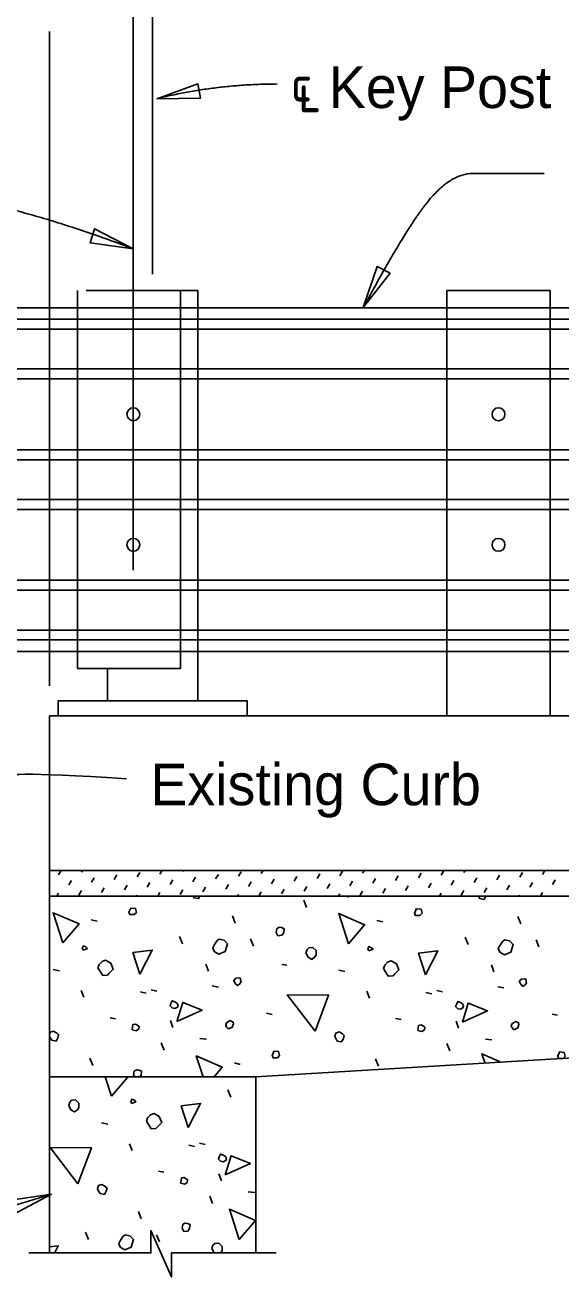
# Model space of a CAD drawing. Extents: x 21526.6 to 21598.7, y 56118.1 to 56155.9.
# Drawn here: x 21554.18 to 21556.78, y 56132.49 to 56138.56 of the extents above; entities that cross this region are included whole.
import ezdxf

# ---------------------------------------------------------------- set-up
doc = ezdxf.new("R2010")
doc.units = 0
for name, color, linetype in [('AdhocPoint_dp', 7, 'Continuous'), ('Border', 7, 'Continuous'), ('Patterning', 7, 'Continuous'), ('PlotBorder_dp', 7, 'Continuous'), ('SheetBorder_dp', 7, 'Continuous')]:
    doc.layers.add(name, color=color, linetype=linetype)

msp = doc.modelspace()

# ---------------------------------------------------------------- linework, layer by layer
at = {"layer": 'AdhocPoint_dp'}
for p, q in [((21554.3017, 56135.21), (21555.3017, 56135.21)), ((21554.3018, 56135.2101), (21554.3018, 56132.6054)), ((21554.3018, 56135.21), (21562.4118, 56135.21)), ((21565.8764, 56134.4601), (21554.3018, 56134.4601)), ((21554.3018, 56134.3351), (21565.8764, 56134.3351)), ((21559.5217, 56133.71), (21555.3017, 56133.4601)), ((21555.3017, 56133.46), (21554.3017, 56133.46)), ((21555.3017, 56133.4601), (21555.3017, 56132.6054))]:
    msp.add_line(p, q, dxfattribs=at)
at = {"layer": 'Patterning'}
for p, q in [((21554.7081, 56135.9163), (21554.7081, 56138.7275)), ((21554.8018, 56138.7275), (21554.8018, 56137.3509)), ((21554.4372, 56137.2725), (21554.4372, 56135.4392)), ((21554.479, 56137.2725), (21555.0205, 56137.2725)), ((21554.9372, 56137.2725), (21554.9372, 56135.4392)), ((21556.2288, 56137.2725), (21556.2288, 56135.21)), ((21556.2288, 56137.2725), (21556.7288, 56137.2725)), ((21556.7288, 56137.2725), (21556.7288, 56135.21)), ((21554.3461, 56134.4388), (21554.3585, 56134.4601)), ((21554.4568, 56134.4517), (21554.4616, 56134.4601)), ((21554.5056, 56134.4029), (21554.5186, 56134.4253)), ((21554.6162, 56134.4159), (21554.6292, 56134.4383)), ((21554.7269, 56134.4288), (21554.7398, 56134.4512)), ((21554.8375, 56134.4418), (21554.8481, 56134.4601)), ((21554.9481, 56134.4548), (21554.9512, 56134.4601)), ((21554.997, 56134.4059), (21555.0099, 56134.4283)), ((21555.1076, 56134.4189), (21555.1206, 56134.4413)), ((21555.2182, 56134.4319), (21555.2312, 56134.4542)), ((21555.3289, 56134.4448), (21555.3377, 56134.4601)), ((21555.4395, 56134.4578), (21555.4409, 56134.4601)), ((21555.4883, 56134.4089), (21555.5013, 56134.4313)), ((21555.599, 56134.4219), (21555.6119, 56134.4443)), ((21555.7096, 56134.4349), (21555.7226, 56134.4573)), ((21555.8202, 56134.4478), (21555.8273, 56134.4601)), ((21555.8691, 56134.399), (21555.882, 56134.4214)), ((21555.9797, 56134.412), (21555.9927, 56134.4344)), ((21556.0903, 56134.4249), (21556.1033, 56134.4473)), ((21556.201, 56134.4379), (21556.2138, 56134.4601)), ((21556.3116, 56134.4509), (21556.317, 56134.4601)), ((21556.3604, 56134.402), (21556.3734, 56134.4244)), ((21556.4711, 56134.415), (21556.484, 56134.4374)), ((21556.5817, 56134.428), (21556.5947, 56134.4503)), ((21556.6923, 56134.4409), (21556.7035, 56134.4601)), ((21554.395, 56134.3899), (21554.4079, 56134.4123)), ((21554.4438, 56134.3411), (21554.4568, 56134.3635)), ((21554.5544, 56134.3541), (21554.5674, 56134.3765)), ((21554.6651, 56134.367), (21554.678, 56134.3894)), ((21554.7757, 56134.38), (21554.7887, 56134.4024)), ((21554.8863, 56134.393), (21554.8993, 56134.4154)), ((21554.9352, 56134.3441), (21554.9481, 56134.3665)), ((21555.0458, 56134.3571), (21555.0588, 56134.3795)), ((21555.1564, 56134.3701), (21555.1694, 56134.3925)), ((21555.2671, 56134.383), (21555.28, 56134.4054)), ((21555.3777, 56134.396), (21555.3907, 56134.4184)), ((21555.4265, 56134.3472), (21555.4395, 56134.3695)), ((21555.5372, 56134.3601), (21555.5501, 56134.3825)), ((21555.6478, 56134.3731), (21555.6608, 56134.3955)), ((21555.7584, 56134.386), (21555.7714, 56134.4084)), ((21555.9179, 56134.3502), (21555.9309, 56134.3726)), ((21556.0285, 56134.3631), (21556.0415, 56134.3855)), ((21556.1392, 56134.3761), (21556.1521, 56134.3985)), ((21556.2498, 56134.3891), (21556.2628, 56134.4115)), ((21556.2986, 56134.3402), (21556.3116, 56134.3626)), ((21556.4093, 56134.3532), (21556.4222, 56134.3756)), ((21556.5199, 56134.3662), (21556.5329, 56134.3885)), ((21556.6305, 56134.3791), (21556.6435, 56134.4015)), ((21556.7412, 56134.3921), (21556.7541, 56134.4145)), ((21554.3372, 56134.3351), (21554.3461, 56134.3505)), ((21554.7237, 56134.3351), (21554.7269, 56134.3406)), ((21554.8268, 56134.3351), (21554.8375, 56134.3536)), ((21555.2133, 56134.3351), (21555.2182, 56134.3436)), ((21555.3164, 56134.3351), (21555.3289, 56134.3566)), ((21555.5488, 56134.2802), (21555.5346, 56134.3156)), ((21555.7029, 56134.3351), (21555.7096, 56134.3466)), ((21555.7313, 56134.3351), (21555.7532, 56134.3326)), ((21555.8073, 56134.3372), (21555.8202, 56134.3596)), ((21556.0894, 56134.3351), (21556.0903, 56134.3367)), ((21556.1925, 56134.3351), (21556.201, 56134.3497)), ((21556.579, 56134.3351), (21556.5817, 56134.3397)), ((21556.6821, 56134.3351), (21556.6923, 56134.3527)), ((21555.2029, 56134.2054), (21555.1888, 56134.2407)), ((21554.5046, 56134.2213), (21554.5329, 56134.2142)), ((21555.8893, 56134.2177), (21555.9176, 56134.2107)), ((21556.5876, 56134.2018), (21556.5734, 56134.2372)), ((21554.9466, 56134.1046), (21554.9324, 56134.1399)), ((21555.2907, 56134.0928), (21555.2765, 56134.1282)), ((21556.3313, 56134.1011), (21556.3171, 56134.1364)), ((21556.6753, 56134.0893), (21556.6612, 56134.1247)), ((21555.0721, 56133.972), (21555.0597, 56134.0056)), ((21555.4286, 56134.0045), (21555.4533, 56134.0009)), ((21556.4568, 56133.9685), (21556.4444, 56134.0021)), ((21554.3196, 56133.9797), (21554.3497, 56133.9744)), ((21555.7043, 56133.9762), (21555.7344, 56133.9709)), ((21554.4681, 56133.8454), (21554.4558, 56133.8789)), ((21554.7945, 56133.8819), (21554.8228, 56133.8748)), ((21555.0909, 56133.9002), (21555.121, 56133.8949)), ((21555.8528, 56133.8418), (21555.8404, 56133.8754)), ((21556.1792, 56133.8783), (21556.2075, 56133.8712)), ((21556.4756, 56133.8966), (21556.5056, 56133.8913)), ((21554.7421, 56133.8719), (21554.7704, 56133.8648)), ((21556.1268, 56133.8683), (21556.1551, 56133.8613)), ((21555.3543, 56133.7676), (21555.3808, 56133.7623)), ((21556.739, 56133.764), (21556.7655, 56133.7587)), ((21554.5954, 56133.7464), (21554.6219, 56133.7411)), ((21554.9006, 56133.6993), (21554.8882, 56133.7328)), ((21555.9801, 56133.7428), (21556.0066, 56133.7375)), ((21556.2853, 56133.6957), (21556.2729, 56133.7293)), ((21555.0308, 56133.6456), (21555.0626, 56133.6421)), ((21556.4155, 56133.6421), (21556.4473, 56133.6385)), ((21554.8582, 56133.5897), (21554.844, 56133.625)), ((21556.2429, 56133.5861), (21556.2287, 56133.6215)), ((21554.5123, 56133.5148), (21554.4982, 56133.5501)), ((21555.1987, 56133.5272), (21555.227, 56133.5201)), ((21555.897, 56133.5112), (21555.8829, 56133.5466)), ((21555.1813, 56133.3611), (21555.1671, 56133.3965)), ((21554.3017, 56133.2612), (21554.3033, 56133.261)), ((21554.5543, 56133.2362), (21554.5844, 56133.2309)), ((21554.7028, 56133.1019), (21554.6905, 56133.1355)), ((21554.9768, 56133.1284), (21555.0051, 56133.1213)), ((21555.0292, 56133.1384), (21555.0575, 56133.1313)), ((21554.8301, 56133.0029), (21554.8566, 56132.9976)), ((21555.1353, 56132.9558), (21555.1229, 56132.9894)), ((21555.0929, 56132.8462), (21555.0787, 56132.8815)), ((21555.2655, 56132.9021), (21555.2973, 56132.8986)), ((21554.747, 56132.7713), (21554.7329, 56132.8067)), ((21554.4907, 56132.6706), (21554.4766, 56132.7059)), ((21554.8348, 56132.6588), (21554.8206, 56132.6942))]:
    msp.add_line(p, q, dxfattribs=at)
for points in [[(21554.9988, 56134.3351), (21555.0031, 56134.3273), (21555.0244, 56134.3238), (21555.0306, 56134.3351)], [(21556.3816, 56134.3351), (21556.3878, 56134.3238), (21556.409, 56134.3203), (21556.4173, 56134.3351)], [(21554.3674, 56134.1088), (21554.3196, 56134.2555), (21554.4452, 56134.2007), (21554.3674, 56134.1088)], [(21554.692, 56134.246), (21554.7132, 56134.246), (21554.7238, 56134.2566), (21554.7185, 56134.2761), (21554.6956, 56134.2778), (21554.692, 56134.2672), (21554.6867, 56134.2584), (21554.692, 56134.246), (21554.6885, 56134.2495)], [(21555.7521, 56134.1052), (21555.7043, 56134.2519), (21555.8298, 56134.1971), (21555.7521, 56134.1052)], [(21556.0767, 56134.2425), (21556.0979, 56134.2425), (21556.1085, 56134.2531), (21556.1032, 56134.2725), (21556.0802, 56134.2743), (21556.0767, 56134.2637), (21556.0714, 56134.2549), (21556.0767, 56134.2425), (21556.0732, 56134.246)], [(21555.4003, 56134.16), (21555.4091, 56134.1441), (21555.4286, 56134.1459), (21555.4374, 56134.1582), (21555.4392, 56134.1777), (21555.4268, 56134.183), (21555.4179, 56134.1848), (21555.4073, 56134.1812), (21555.4038, 56134.1777), (21555.4003, 56134.16)], [(21555.1004, 56134.0675), (21555.1234, 56134.0551), (21555.1534, 56134.0675), (21555.1658, 56134.1046), (21555.1481, 56134.1223), (21555.1251, 56134.1276), (21555.1145, 56134.1205), (21555.1021, 56134.1011), (21555.0933, 56134.0851), (21555.1004, 56134.0675)], [(21556.485, 56134.0639), (21556.508, 56134.0516), (21556.5381, 56134.0639), (21556.5505, 56134.1011), (21556.5328, 56134.1187), (21556.5098, 56134.124), (21556.4992, 56134.117), (21556.4868, 56134.0975), (21556.478, 56134.0816), (21556.485, 56134.0639)], [(21554.4664, 56134.0734), (21554.4858, 56134.0822), (21554.4787, 56134.0893), (21554.4664, 56134.0946), (21554.4611, 56134.0822), (21554.4664, 56134.0734)], [(21554.7397, 56133.9579), (21554.7062, 56134.0622), (21554.7999, 56134.0745), (21554.7397, 56133.9579)], [(21555.5452, 56134.061), (21555.5558, 56134.0398), (21555.5735, 56134.0292), (21555.5876, 56134.0398), (21555.5947, 56134.0504), (21555.5947, 56134.0716), (21555.5788, 56134.0875), (21555.5594, 56134.0858), (21555.5505, 56134.0769), (21555.5452, 56134.061)], [(21555.851, 56134.0699), (21555.8705, 56134.0787), (21555.8634, 56134.0858), (21555.851, 56134.0911), (21555.8457, 56134.0787), (21555.851, 56134.0699)], [(21556.1244, 56133.9543), (21556.0908, 56134.0586), (21556.1845, 56134.071), (21556.1244, 56133.9543)], [(21554.5371, 56133.9885), (21554.5601, 56133.9514), (21554.583, 56133.9532), (21554.5919, 56133.962), (21554.6113, 56133.9815), (21554.599, 56134.0115), (21554.5742, 56134.0257), (21554.5565, 56134.0186), (21554.5424, 56134.0045), (21554.5371, 56133.9885)], [(21555.9218, 56133.985), (21555.9447, 56133.9479), (21555.9677, 56133.9497), (21555.9766, 56133.9585), (21555.996, 56133.9779), (21555.9836, 56134.008), (21555.9589, 56134.0221), (21555.9412, 56134.0151), (21555.9271, 56134.0009), (21555.9218, 56133.985)], [(21555.2023, 56133.9125), (21555.2129, 56133.9019), (21555.2235, 56133.909), (21555.2306, 56133.9196), (21555.227, 56133.9373), (21555.2182, 56133.939), (21555.2058, 56133.9373), (21555.1952, 56133.9267), (21555.2023, 56133.9125)], [(21556.587, 56133.909), (21556.5976, 56133.8984), (21556.6082, 56133.9055), (21556.6152, 56133.9161), (21556.6117, 56133.9337), (21556.6029, 56133.9355), (21556.5905, 56133.9337), (21556.5799, 56133.9231), (21556.587, 56133.909)], [(21554.8971, 56133.7935), (21554.9095, 56133.7917), (21554.9218, 56133.797), (21554.9254, 56133.8076), (21554.9201, 56133.8164), (21554.9095, 56133.8235), (21554.8971, 56133.8288), (21554.89, 56133.8147), (21554.8865, 56133.8041), (21554.8971, 56133.7935)], [(21554.9194, 56133.7287), (21554.9477, 56133.8206), (21555.0414, 56133.7835), (21554.9194, 56133.7287)], [(21555.5894, 56133.681), (21555.4551, 56133.8577), (21555.6548, 56133.856), (21555.5894, 56133.681)], [(21556.2818, 56133.7899), (21556.2941, 56133.7882), (21556.3065, 56133.7935), (21556.31, 56133.8041), (21556.3047, 56133.8129), (21556.2941, 56133.82), (21556.2818, 56133.8253), (21556.2747, 56133.8111), (21556.2711, 56133.8005), (21556.2818, 56133.7899)], [(21556.3041, 56133.7251), (21556.3324, 56133.8171), (21556.4261, 56133.7799), (21556.3041, 56133.7251)], [(21554.7033, 56133.688), (21554.7227, 56133.6827), (21554.7351, 56133.6916), (21554.7368, 56133.7039), (21554.7333, 56133.7075), (21554.7192, 56133.7145), (21554.7068, 56133.7128), (21554.705, 56133.7004), (21554.7033, 56133.688)], [(21555.1669, 56133.6933), (21555.174, 56133.6933), (21555.1881, 56133.7004), (21555.1934, 56133.7163), (21555.1917, 56133.7251), (21555.1775, 56133.7322), (21555.1598, 56133.7216), (21555.1563, 56133.711), (21555.1598, 56133.7004), (21555.1669, 56133.6933)], [(21556.0879, 56133.6845), (21556.1074, 56133.6792), (21556.1197, 56133.688), (21556.1215, 56133.7004), (21556.118, 56133.7039), (21556.1038, 56133.711), (21556.0915, 56133.7092), (21556.0897, 56133.6969), (21556.0879, 56133.6845)], [(21556.5516, 56133.6898), (21556.5587, 56133.6898), (21556.5728, 56133.6969), (21556.5781, 56133.7128), (21556.5763, 56133.7216), (21556.5622, 56133.7287), (21556.5445, 56133.7181), (21556.541, 56133.7075), (21556.5445, 56133.6969), (21556.5516, 56133.6898)], [(21554.3037, 56133.6527), (21554.3126, 56133.6368), (21554.3338, 56133.6332), (21554.3426, 56133.6491), (21554.3462, 56133.6633), (21554.3373, 56133.6721), (21554.3214, 56133.681), (21554.3055, 56133.6756), (21554.3017, 56133.6643)], [(21554.3017, 56133.6567), (21554.3037, 56133.6527)], [(21555.6884, 56133.6491), (21555.6973, 56133.6332), (21555.7185, 56133.6297), (21555.7273, 56133.6456), (21555.7308, 56133.6597), (21555.722, 56133.6686), (21555.7061, 56133.6774), (21555.6902, 56133.6721), (21555.6849, 56133.6562), (21555.6884, 56133.6491)], [(21555.3861, 56133.5519), (21555.4073, 56133.5519), (21555.4179, 56133.5625), (21555.4126, 56133.582), (21555.3897, 56133.5837), (21555.3861, 56133.5731), (21555.3808, 56133.5643), (21555.3861, 56133.5519), (21555.3826, 56133.5554)], [(21556.4121, 56133.5297), (21556.3984, 56133.5719), (21556.4846, 56133.5343)], [(21556.7708, 56133.5484), (21556.792, 56133.5484), (21556.8026, 56133.559), (21556.7973, 56133.5784), (21556.7743, 56133.5802), (21556.7708, 56133.5696), (21556.7655, 56133.5607), (21556.7708, 56133.5484), (21556.7673, 56133.5519)], [(21555.0467, 56133.46), (21555.0138, 56133.5614), (21555.1393, 56133.5066), (21555.0999, 56133.46)], [(21554.6021, 56133.3653), (21554.5713, 56133.46)], [(21554.6734, 56133.46), (21554.6798, 56133.4572), (21554.6021, 56133.3653)], [(21554.7413, 56133.46), (21554.7468, 56133.4677), (21554.7486, 56133.4871), (21554.7362, 56133.4924), (21554.7274, 56133.4942), (21554.7168, 56133.4907), (21554.7132, 56133.4871), (21554.7097, 56133.4694)], [(21554.7097, 56133.4694), (21554.7149, 56133.46)], [(21554.3952, 56133.3211), (21554.4058, 56133.2999), (21554.4235, 56133.2893), (21554.4377, 56133.2999), (21554.4447, 56133.3105), (21554.4447, 56133.3317), (21554.4288, 56133.3476), (21554.4094, 56133.3458), (21554.4005, 56133.337), (21554.3952, 56133.3211)], [(21554.7011, 56133.3299), (21554.7205, 56133.3388), (21554.7134, 56133.3458), (21554.7011, 56133.3511), (21554.6958, 56133.3388), (21554.7011, 56133.3299)], [(21554.9744, 56133.2144), (21554.9409, 56133.3187), (21555.0345, 56133.3311), (21554.9744, 56133.2144)], [(21554.7718, 56133.2451), (21554.7948, 56133.208), (21554.8177, 56133.2097), (21554.8266, 56133.2186), (21554.846, 56133.238), (21554.8336, 56133.2681), (21554.8089, 56133.2822), (21554.7912, 56133.2751), (21554.7771, 56133.261), (21554.7718, 56133.2451)], [(21554.4394, 56132.941), (21554.3051, 56133.1178), (21554.5048, 56133.116), (21554.4394, 56132.941)], [(21555.1318, 56133.05), (21555.1441, 56133.0482), (21555.1565, 56133.0535), (21555.1601, 56133.0641), (21555.1548, 56133.073), (21555.1441, 56133.0801), (21555.1318, 56133.0854), (21555.1247, 56133.0712), (21555.1212, 56133.0606), (21555.1318, 56133.05)], [(21555.1541, 56132.9852), (21555.1824, 56133.0771), (21555.2761, 56133.04), (21555.1541, 56132.9852)], [(21554.9379, 56132.9446), (21554.9574, 56132.9393), (21554.9698, 56132.9481), (21554.9715, 56132.9605), (21554.968, 56132.964), (21554.9539, 56132.9711), (21554.9415, 56132.9693), (21554.9397, 56132.9569), (21554.9379, 56132.9446)], [(21554.5384, 56132.9092), (21554.5473, 56132.8933), (21554.5685, 56132.8898), (21554.5773, 56132.9057), (21554.5809, 56132.9198), (21554.572, 56132.9287), (21554.5561, 56132.9375), (21554.5402, 56132.9322), (21554.5349, 56132.9163), (21554.5384, 56132.9092)], [(21555.2222, 56132.6712), (21555.1745, 56132.8179), (21555.3, 56132.7631), (21555.2222, 56132.6712)], [(21554.9444, 56132.726), (21554.9532, 56132.7101), (21554.9727, 56132.7118), (21554.9815, 56132.7242), (21554.9833, 56132.7437), (21554.9709, 56132.749), (21554.9621, 56132.7507), (21554.9515, 56132.7472), (21554.9479, 56132.7437), (21554.9444, 56132.726)], [(21554.6445, 56132.6334), (21554.6675, 56132.6211), (21554.6975, 56132.6334), (21554.7099, 56132.6706), (21554.6922, 56132.6882), (21554.6692, 56132.6935), (21554.6586, 56132.6865), (21554.6463, 56132.667), (21554.6374, 56132.6511), (21554.6445, 56132.6334)], [(21554.3018, 56132.6349), (21554.344, 56132.6405), (21554.3259, 56132.6054)], [(21555.1313, 56132.6054), (21555.1318, 56132.6058), (21555.1388, 56132.6164), (21555.1388, 56132.6376), (21555.1229, 56132.6535), (21555.1035, 56132.6517), (21555.0946, 56132.6429), (21555.0893, 56132.627)], [(21555.0893, 56132.627), (21555.1, 56132.6058), (21555.1005, 56132.6054)]]:
    msp.add_lwpolyline(points, dxfattribs=at)
for centre in [(21554.7081, 56136.6724), (21554.7081, 56136.0393)]:
    msp.add_circle(centre, 0.0312, dxfattribs=at)
at = {"layer": 'PlotBorder_dp'}
msp.add_line((21554.3017, 56135.3555), (21554.3017, 56138.5276), dxfattribs=at)
for points in [[(21554.8226, 56138.2024), (21555.0213, 56138.2741), (21555.0338, 56138.2047)], [(21554.7081, 56137.4747), (21554.5204, 56137.5715), (21554.4989, 56137.5043)], [(21555.8233, 56137.1892), (21555.9529, 56137.356), (21555.8907, 56137.3893)], [(21554.3117, 56132.8915), (21554.1029, 56132.8596), (21554.1251, 56132.7926)]]:
    msp.add_lwpolyline(points, close=True, dxfattribs=at)
msp.add_lwpolyline([(21555.4017, 56132.6055), (21554.8932, 56132.6055), (21554.8932, 56132.4893), (21554.7938, 56132.7143), (21554.7938, 56132.6055), (21554.2018, 56132.6055)], dxfattribs=at)
for points, degree in [([(21554.8226, 56138.2028), (21555.1141, 56138.2737), (21555.4056, 56138.2737)], 2), ([(21556.6997, 56137.8396), (21556.4594, 56137.8396), (21556.2473, 56137.8396), (21556.0283, 56137.571), (21555.8233, 56137.1892)], 2), ([(21552.581, 56137.751), (21553.1726, 56137.7569), (21553.9973, 56137.7421), (21554.7081, 56137.4746)], 2), ([(21554.6745, 56134.9046), (21554.1531, 56134.9384), (21554.0496, 56134.9162), (21553.9557, 56134.8796), (21553.7845, 56134.6171)], 3), ([(21554.3117, 56132.8915), (21553.648, 56132.6719), (21552.9843, 56132.6719)], 2)]:
    msp.add_open_spline(points, degree=degree, dxfattribs=at)
at = {"layer": 'SheetBorder_dp'}
for p, q in [((21555.0205, 56137.2725), (21555.0205, 56135.283)), ((21564.1633, 56137.1891), (21552.8484, 56137.1891)), ((21552.8484, 56137.1336), (21564.1633, 56137.1336)), ((21552.8484, 56137.0853), (21564.1633, 56137.0853)), ((21552.8484, 56136.8925), (21564.1633, 56136.8925)), ((21552.8484, 56136.8443), (21564.1633, 56136.8443)), ((21552.8484, 56136.5003), (21564.1633, 56136.5003)), ((21552.8484, 56136.4521), (21564.1633, 56136.4521)), ((21552.8484, 56136.2593), (21564.1633, 56136.2593)), ((21552.8484, 56136.2112), (21564.1633, 56136.2112)), ((21552.8484, 56135.8672), (21564.1633, 56135.8672)), ((21552.8484, 56135.819), (21564.1633, 56135.819)), ((21552.8484, 56135.6262), (21564.1633, 56135.6262)), ((21552.8484, 56135.5779), (21564.1633, 56135.5779)), ((21564.1633, 56135.5224), (21552.8484, 56135.5224)), ((21554.9372, 56135.4392), (21554.4372, 56135.4392)), ((21554.583, 56135.4392), (21554.583, 56135.283))]:
    msp.add_line(p, q, dxfattribs=at)
msp.add_lwpolyline([(21554.3434, 56135.21), (21554.3434, 56135.283), (21555.2601, 56135.283), (21555.2601, 56135.21)], close=True, dxfattribs=at)
for centre in [(21556.4788, 56136.6724), (21556.4788, 56136.0393)]:
    msp.add_circle(centre, 0.0312, dxfattribs=at)

# ---------------------------------------------------------------- texts
at = {"layer": 'Border'}
for s, p in [('℄ Key Post', (21555.4716, 56138.1571)), ('Existing Curb', (21554.7907, 56134.7766))]:
    msp.add_text(s, height=0.2016, dxfattribs=at).set_placement(p)

doc.saveas('drawing.dxf')
